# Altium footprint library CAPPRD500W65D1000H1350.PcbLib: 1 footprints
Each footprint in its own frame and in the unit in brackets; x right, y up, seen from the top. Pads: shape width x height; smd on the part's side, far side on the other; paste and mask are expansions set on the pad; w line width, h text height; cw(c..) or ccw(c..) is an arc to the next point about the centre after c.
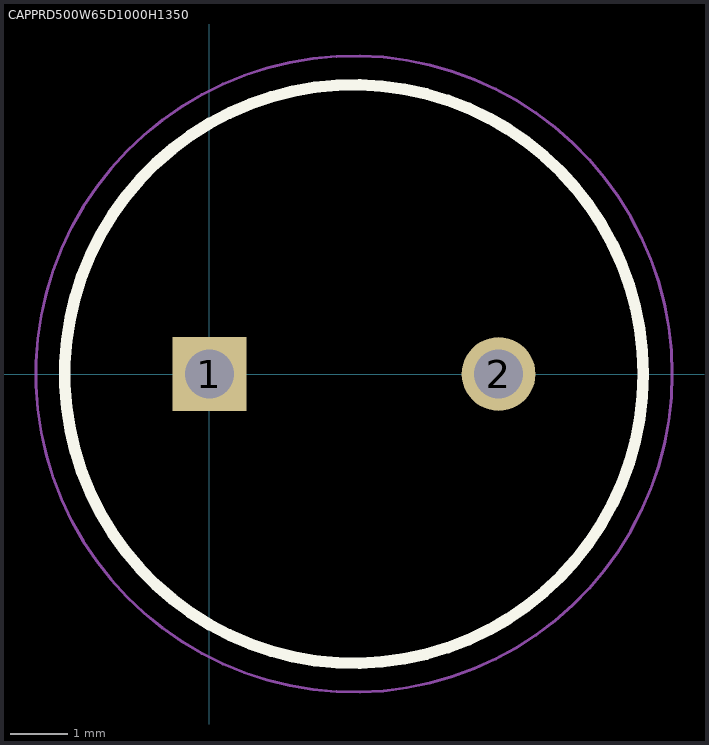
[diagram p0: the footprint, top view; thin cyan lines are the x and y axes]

## CAPPRD500W65D1000H1350 [mm]
pads (2):
  rect 1.275x1.275 / inner round 1.275 / far side rect 1.275x1.275 hole 0.85: 1(0,0)
  round 1.275 hole 0.85: 2(5,0)
Top Overlay:
  circle w0.2: c2.5,0 r5
Mechanical 15:
  circle w0.1: c2.5,0 r5
Mechanical 20:
  circle w0.05: c2.5,0 r5.5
